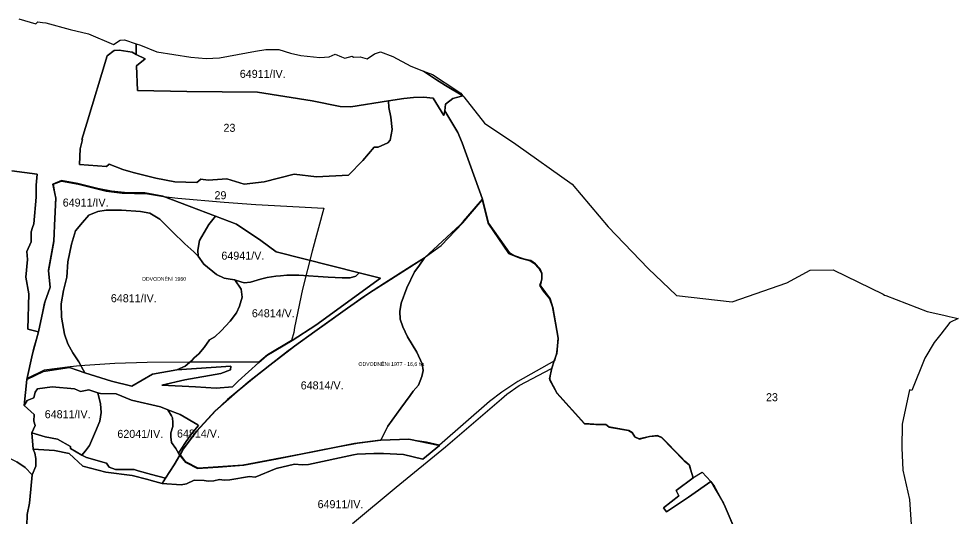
# Model space of a CAD drawing. Extents: x -521621 to -516761, y -1190184 to -1184927.
# Drawn here: x -518679 to -516919, y -1186003 to -1185071 of the extents above; entities that cross this region are included whole.
import ezdxf

# ---------------------------------------------------------------- set-up
doc = ezdxf.new("R2010")
doc.units = 0
doc.layers.add('BPEJ_s', color=7, linetype='Continuous')
doc.layers.add('odvodneni_s', color=7, linetype='Continuous')

msp = doc.modelspace()

# ---------------------------------------------------------------- linework, layer by layer
at = {"layer": 'BPEJ_s'}
for points in [[(-518679, -1185071.3), (-518647.2, -1185080.5), (-518643.2, -1185077.1), (-518634.5, -1185078.2), (-518628.2, -1185079.1), (-518582.7, -1185091.5), (-518548.4, -1185099.6), (-518501.4, -1185119.5), (-518489.2, -1185111.4), (-518480.6, -1185110.5), (-518459.1, -1185118.3), (-518459, -1185138.2), (-518466.2, -1185134), (-518491.1, -1185130.2), (-518500.3, -1185130.4), (-518513.4, -1185140.4), (-518551.6, -1185266.9), (-518560.8, -1185297), (-518559.4, -1185297.5), (-518563.8, -1185315), (-518565.4, -1185344.1), (-518514.8, -1185348.1), (-518509.7, -1185343.3), (-518484.1, -1185353.2), (-518464.8, -1185359.2), (-518421.9, -1185369.5), (-518386.4, -1185376.4), (-518345.6, -1185377.5), (-518337.7, -1185371.7), (-518324.2, -1185373.5), (-518289, -1185370.8), (-518256.6, -1185380.8), (-518219.2, -1185376.4), (-518163.2, -1185362.1), (-518121.4, -1185367.5), (-518060.9, -1185364), (-518034.2, -1185336.9), (-518013.4, -1185311.7), (-518005.8, -1185311.4), (-517987.2, -1185303.4), (-517983.2, -1185298.5), (-517979.6, -1185278.5), (-517981.6, -1185255.6), (-517985.7, -1185237.6), (-517986.1, -1185224.9), (-517957.4, -1185220.3), (-517939.5, -1185218.8), (-517920.8, -1185218.3), (-517902.4, -1185219.9), (-517882.7, -1185252.1), (-517880.7, -1185243.4), (-517856.1, -1185284), (-517848.3, -1185303.8), (-517810.2, -1185409.1), (-517845.7, -1185450.4), (-517851.9, -1185457.2), (-517918.9, -1185518.6), (-517943.6, -1185534.2), (-517993.6, -1185566.2), (-518025.5, -1185586.9), (-518063, -1185613), (-518124.5, -1185656.9), (-518162.4, -1185684.1), (-518208.8, -1185720), (-518241.2, -1185745.3), (-518288, -1185784.3), (-518310, -1185804.6), (-518346.2, -1185844), (-518370.7, -1185877), (-518377.1, -1185888.1), (-518379.6, -1185884.4), (-518373.5, -1185875.2), (-518366.3, -1185864.4), (-518355.6, -1185848.3), (-518342.1, -1185833.1), (-518343.5, -1185831.8), (-518376.8, -1185812.3), (-518399.9, -1185803.2), (-518413.6, -1185797.7), (-518468, -1185785.2), (-518496.6, -1185773.6), (-518525.7, -1185773), (-518530.9, -1185771.4), (-518547.9, -1185766.2), (-518563.4, -1185769), (-518574.7, -1185764.4), (-518616.5, -1185760.2), (-518643.8, -1185764.2), (-518648.3, -1185770.1), (-518650.8, -1185781.2), (-518663.1, -1185786), (-518669.1, -1185795.6), (-518664, -1185746.6), (-518632.5, -1185731.4), (-518583.8, -1185724.2), (-518555, -1185734.5), (-518505.4, -1185750.1), (-518467, -1185759), (-518428.2, -1185736.5), (-518382.8, -1185728.3), (-518281.6, -1185722), (-518282, -1185728.7), (-518300.5, -1185735.5), (-518368, -1185747.2), (-518410.8, -1185757.1), (-518347.6, -1185760.4), (-518309.2, -1185762.6), (-518278.6, -1185760.3), (-518267.9, -1185749.8), (-518229.3, -1185714.9), (-518213.9, -1185701.5), (-518166.7, -1185673.6), (-518122.2, -1185644.8), (-518001.2, -1185557), (-518041, -1185547), (-518196.6, -1185507.8), (-518225.5, -1185486.3), (-518270.8, -1185456.1), (-518310.3, -1185441), (-518409, -1185403.2), (-518442.6, -1185396.9), (-518480.8, -1185396.3), (-518505.2, -1185394.3), (-518530.8, -1185388.8), (-518568.4, -1185379.5), (-518598.8, -1185374.3), (-518615.3, -1185381.1), (-518609.5, -1185407.2), (-518612, -1185458.3), (-518613.3, -1185488.4), (-518623.3, -1185543.2), (-518620.4, -1185573.5), (-518629.8, -1185602.1), (-518641.9, -1185657.5), (-518662, -1185652.7), (-518660.1, -1185586.3), (-518665.4, -1185554.9), (-518662.7, -1185522.1), (-518664, -1185506.8), (-518655.9, -1185488.8), (-518655.7, -1185469.9), (-518653.2, -1185462.2), (-518650.9, -1185455.3), (-518646.4, -1185405.3), (-518646.1, -1185382.5), (-518644.7, -1185362.2), (-518692, -1185355.7)], [(-517323.2, -1186060.8), (-517357.4, -1185980.5), (-517373.4, -1185950.9), (-517375.6, -1185947.1), (-517382.3, -1185937.7), (-517424.2, -1185967), (-517465.3, -1185994.3), (-517471, -1185987), (-517442.6, -1185964.7), (-517447.2, -1185954.4), (-517415.7, -1185930.7), (-517422.7, -1185906.3), (-517430.9, -1185899.6), (-517437.9, -1185891.9), (-517474.4, -1185855.1), (-517482.6, -1185851.8), (-517497.5, -1185853.7), (-517516.5, -1185857.8), (-517525, -1185854.2), (-517529.9, -1185846), (-517536.1, -1185842.3), (-517573.7, -1185835.2), (-517579, -1185830.9), (-517592.9, -1185831.1), (-517619, -1185829.2), (-517670.8, -1185771.5), (-517684.5, -1185745.7), (-517680, -1185725.3), (-517675.6, -1185711.7), (-517671.2, -1185697.7), (-517668.6, -1185669), (-517678.5, -1185611.7), (-517683.6, -1185595.4), (-517700.8, -1185571.8), (-517701.8, -1185569.7), (-517698.7, -1185557.9), (-517698.7, -1185547.3), (-517702.7, -1185538.6), (-517710.9, -1185529.8), (-517719.3, -1185524), (-517731.6, -1185521.1), (-517751.5, -1185514.3), (-517759.6, -1185509.5), (-517799.1, -1185453.7), (-517810.2, -1185409.1), (-517848.3, -1185303.8), (-517856.1, -1185284), (-517880.7, -1185243.4), (-517879.4, -1185231.3), (-517865.9, -1185220.3), (-517846.8, -1185215.4), (-517845.4, -1185217.3), (-517806.7, -1185267), (-517747.8, -1185305.8), (-517642.2, -1185380.8), (-517574.8, -1185460.6), (-517499.9, -1185539), (-517446.5, -1185589.5), (-517342.5, -1185601.1), (-517240, -1185565.8), (-517196.5, -1185541.9), (-517153.2, -1185541.5), (-517059.7, -1185587.2), (-517057.2, -1185588.5), (-517054.6, -1185589.7), (-517016, -1185604.6), (-516977.3, -1185619.4), (-516946, -1185626.5), (-516936, -1185628.7), (-516918.9, -1185632.5), (-516934.4, -1185639.9), (-516951.6, -1185661.5), (-516964.2, -1185677.4), (-516981.2, -1185707), (-517005.8, -1185767.5), (-517010.3, -1185766.1), (-517023.9, -1185830.2), (-517024.8, -1185874.8), (-517022.7, -1185916.5), (-517010.1, -1185971.5), (-517003.7, -1186064.1)], [(-518692, -1185355.7), (-518644.7, -1185362.2), (-518646.1, -1185382.5), (-518646.4, -1185405.3), (-518650.9, -1185455.3), (-518653.2, -1185462.2), (-518655.7, -1185469.9), (-518655.9, -1185488.8), (-518664, -1185506.8), (-518662.7, -1185522.1), (-518665.4, -1185554.9), (-518660.1, -1185586.3), (-518662, -1185652.7), (-518641.9, -1185657.5), (-518653.2, -1185698.9), (-518664, -1185746.6), (-518669.1, -1185795.6), (-518650.1, -1185812.4), (-518650.6, -1185824.9), (-518648.2, -1185832.5), (-518654.3, -1185846.7), (-518651.9, -1185877), (-518648.8, -1185884.7), (-518647.2, -1185894.9), (-518646.8, -1185908.9), (-518653.6, -1185925.2), (-518666.9, -1185911.6), (-518682.3, -1185900.6)], [(-518663.9, -1186020.8), (-518663.3, -1185999.2), (-518658.6, -1185978.5), (-518656.2, -1185952.1), (-518653.6, -1185925.2), (-518646.8, -1185908.9), (-518647.2, -1185894.9), (-518648.8, -1185884.7), (-518651.9, -1185877), (-518611.8, -1185879.4), (-518584.7, -1185885.5), (-518558.6, -1185909.1), (-518516.1, -1185919.9), (-518466.5, -1185926.5), (-518437.2, -1185934.1), (-518431.1, -1185935.5), (-518410.3, -1185941.2), (-518374.6, -1185943.8), (-518364.4, -1185941.9), (-518350.4, -1185935.4), (-518331.8, -1185935.8), (-518323.9, -1185937), (-518313.7, -1185936.5), (-518303.1, -1185933.8), (-518294, -1185935.1), (-518283.4, -1185934.7), (-518246.4, -1185928.1), (-518236.3, -1185929.6), (-518196.9, -1185913.2), (-518162.3, -1185905.3), (-518147.9, -1185906.4), (-518135.9, -1185905.7), (-518052.1, -1185887.8), (-518044.7, -1185886.5), (-518013.7, -1185885.3), (-517995.8, -1185885.5), (-517958.2, -1185887.3), (-517921.7, -1185896.1), (-517891, -1185870), (-517948.4, -1185858.7), (-518000.9, -1185860.3), (-517987.2, -1185834), (-517963.3, -1185800.4), (-517945.9, -1185776.5), (-517940.1, -1185768.3), (-517930.3, -1185757.1), (-517923.9, -1185740.9), (-517921, -1185729.6), (-517922.9, -1185717.3), (-517933.2, -1185695.2), (-517950.9, -1185666.7), (-517959.2, -1185648.1), (-517964.6, -1185633.4), (-517965.1, -1185619.6), (-517962.7, -1185603.9), (-517951.9, -1185575), (-517937.8, -1185544.9), (-517929.2, -1185534.7), (-517918.9, -1185518.6), (-517851.9, -1185457.2), (-517845.7, -1185450.4), (-517810.2, -1185409.1), (-517799.1, -1185453.7), (-517759.6, -1185509.5), (-517751.5, -1185514.3), (-517731.6, -1185521.1), (-517719.3, -1185524), (-517710.9, -1185529.8), (-517702.7, -1185538.6), (-517698.7, -1185547.3), (-517698.7, -1185557.9), (-517701.8, -1185569.7), (-517700.8, -1185571.8), (-517683.6, -1185595.4), (-517678.5, -1185611.7), (-517668.6, -1185669), (-517671.2, -1185697.7), (-517675.6, -1185711.7), (-517680, -1185725.3), (-517684.5, -1185745.7), (-517670.8, -1185771.5), (-517619, -1185829.2), (-517592.9, -1185831.1), (-517579, -1185830.9), (-517573.7, -1185835.2), (-517536.1, -1185842.3), (-517529.9, -1185846), (-517525, -1185854.2), (-517516.5, -1185857.8), (-517497.5, -1185853.7), (-517482.6, -1185851.8), (-517474.4, -1185855.1), (-517437.9, -1185891.9), (-517430.9, -1185899.6), (-517422.7, -1185906.3), (-517415.7, -1185930.7), (-517447.2, -1185954.4), (-517442.6, -1185964.7), (-517471, -1185987), (-517465.3, -1185994.3), (-517424.2, -1185967), (-517382.3, -1185937.7), (-517375.6, -1185947.1), (-517373.4, -1185950.9), (-517357.4, -1185980.5), (-517323.2, -1186060.8)], [(-518758, -1186004.2), (-518755.3, -1185978.2), (-518749.1, -1185953.6), (-518738.2, -1185920.1), (-518722.8, -1185904.4), (-518704.5, -1185895), (-518694.1, -1185895.3), (-518682.3, -1185900.6), (-518666.9, -1185911.6), (-518653.6, -1185925.2), (-518656.2, -1185952.1), (-518658.6, -1185978.5), (-518663.3, -1185999.2), (-518663.9, -1186020.8)]]:
    msp.add_lwpolyline(points, dxfattribs=at)
for points in [[(-518459, -1185138.2), (-518442.2, -1185146.2), (-518458.1, -1185159.6), (-518456.5, -1185205.7), (-518364.3, -1185207.5), (-518231.7, -1185208.5), (-518129, -1185224.7), (-518076.5, -1185235.8), (-518057, -1185236.3), (-517986.1, -1185224.9), (-517985.7, -1185237.6), (-517981.6, -1185255.6), (-517979.6, -1185278.5), (-517983.2, -1185298.5), (-517987.2, -1185303.4), (-518005.8, -1185311.4), (-518013.4, -1185311.7), (-518034.2, -1185336.9), (-518060.9, -1185364), (-518121.4, -1185367.5), (-518163.2, -1185362.1), (-518219.2, -1185376.4), (-518256.6, -1185380.8), (-518289, -1185370.8), (-518324.2, -1185373.5), (-518337.7, -1185371.7), (-518345.6, -1185377.5), (-518386.4, -1185376.4), (-518421.9, -1185369.5), (-518464.8, -1185359.2), (-518484.1, -1185353.2), (-518509.7, -1185343.3), (-518514.8, -1185348.1), (-518565.4, -1185344.1), (-518563.8, -1185315), (-518559.4, -1185297.5), (-518560.8, -1185297), (-518551.6, -1185266.9), (-518513.4, -1185140.4), (-518500.3, -1185130.4), (-518491.1, -1185130.2), (-518466.2, -1185134)], [(-518459.1, -1185118.3), (-518450.7, -1185120.4), (-518420.2, -1185133.3), (-518356.7, -1185143.4), (-518327.9, -1185145.4), (-518302.8, -1185144.3), (-518235.6, -1185132.2), (-518216, -1185129), (-518191.5, -1185128.7), (-518169.8, -1185135.4), (-518150.8, -1185140.3), (-518114.6, -1185143.9), (-518097.6, -1185142.5), (-518086.4, -1185137.6), (-518074.5, -1185142.8), (-518068.2, -1185145.1), (-518054.6, -1185141.3), (-518051.7, -1185143.4), (-518039.3, -1185142.2), (-518026.3, -1185146.5), (-518012.5, -1185136.7), (-518001.2, -1185133), (-517978.2, -1185142.1), (-517944.2, -1185159.8), (-517936.5, -1185162.9), (-517928.9, -1185166.1), (-517920.5, -1185169.2), (-517898, -1185184.3), (-517879.4, -1185196.2), (-517846.8, -1185215.4), (-517865.9, -1185220.3), (-517879.4, -1185231.3), (-517880.7, -1185243.4), (-517882.7, -1185252.1), (-517902.4, -1185219.9), (-517920.8, -1185218.3), (-517939.5, -1185218.8), (-517957.4, -1185220.3), (-517986.1, -1185224.9), (-518057, -1185236.3), (-518076.5, -1185235.8), (-518129, -1185224.7), (-518231.7, -1185208.5), (-518364.3, -1185207.5), (-518456.5, -1185205.7), (-518458.1, -1185159.6), (-518442.2, -1185146.2), (-518459, -1185138.2)], [(-517920.5, -1185169.2), (-517903.8, -1185175.3), (-517858.2, -1185205.3), (-517850.7, -1185210.3), (-517846.8, -1185215.4), (-517879.4, -1185196.2), (-517898, -1185184.3)], [(-518664, -1185746.6), (-518653.2, -1185698.9), (-518641.9, -1185657.5), (-518629.8, -1185602.1), (-518620.4, -1185573.5), (-518623.3, -1185543.2), (-518613.3, -1185488.4), (-518612, -1185458.3), (-518609.5, -1185407.2), (-518615.3, -1185381.1), (-518598.8, -1185374.3), (-518568.4, -1185379.5), (-518530.8, -1185388.8), (-518505.2, -1185394.3), (-518480.8, -1185396.3), (-518442.6, -1185396.9), (-518409, -1185403.2), (-518310.3, -1185441), (-518322.7, -1185456.6), (-518340.4, -1185486.3), (-518343.2, -1185504.6), (-518342.6, -1185515.8), (-518351, -1185507.9), (-518368.1, -1185492.8), (-518391.1, -1185470.1), (-518414.6, -1185446.5), (-518433.6, -1185435.1), (-518451, -1185432.2), (-518486.6, -1185429.4), (-518515.1, -1185429.4), (-518530.5, -1185432.2), (-518547.9, -1185439), (-518559.6, -1185452.4), (-518572.5, -1185468.4), (-518580.4, -1185493.3), (-518587.2, -1185526.1), (-518589, -1185555), (-518594.9, -1185580), (-518599.7, -1185605.1), (-518598.7, -1185630.1), (-518593.4, -1185661.8), (-518587.2, -1185680.1), (-518577.5, -1185697), (-518566.3, -1185713.6), (-518561.6, -1185723.2), (-518555, -1185734.5), (-518583.8, -1185724.2), (-518632.5, -1185731.4)], [(-518555, -1185734.5), (-518561.6, -1185723.2), (-518566.3, -1185713.6), (-518577.5, -1185697), (-518587.2, -1185680.1), (-518593.4, -1185661.8), (-518598.7, -1185630.1), (-518599.7, -1185605.1), (-518594.9, -1185580), (-518589, -1185555), (-518587.2, -1185526.1), (-518580.4, -1185493.3), (-518572.5, -1185468.4), (-518559.6, -1185452.4), (-518547.9, -1185439), (-518530.5, -1185432.2), (-518515.1, -1185429.4), (-518486.6, -1185429.4), (-518451, -1185432.2), (-518433.6, -1185435.1), (-518414.6, -1185446.5), (-518391.1, -1185470.1), (-518368.1, -1185492.8), (-518351, -1185507.9), (-518342.6, -1185515.8), (-518332.5, -1185530.6), (-518308.2, -1185550.2), (-518294.4, -1185556.9), (-518282.9, -1185558.5), (-518274.1, -1185560.1), (-518262.4, -1185577.4), (-518260.5, -1185592.4), (-518265.3, -1185609.4), (-518270.9, -1185621.8), (-518282.6, -1185637.4), (-518299.6, -1185655.4), (-518311.6, -1185666.5), (-518321.4, -1185672.3), (-518331.5, -1185686.7), (-518341.3, -1185698.7), (-518350.3, -1185706.3), (-518354.6, -1185711.4), (-518367, -1185722), (-518382.8, -1185728.3), (-518428.2, -1185736.5), (-518467, -1185759), (-518505.4, -1185750.1)], [(-518342.6, -1185515.8), (-518343.2, -1185504.6), (-518340.4, -1185486.3), (-518322.7, -1185456.6), (-518310.3, -1185441), (-518270.8, -1185456.1), (-518225.5, -1185486.3), (-518196.6, -1185507.8), (-518041, -1185547), (-518047.4, -1185553), (-518058.2, -1185556.2), (-518073.2, -1185556.5), (-518099.4, -1185554.8), (-518117.9, -1185554.1), (-518154.2, -1185551.3), (-518176.5, -1185551.6), (-518188.7, -1185552.3), (-518197.2, -1185553), (-518213.8, -1185555.6), (-518226.2, -1185558.8), (-518245.1, -1185564.7), (-518256.9, -1185565.7), (-518271.2, -1185561.1), (-518274.1, -1185560.1), (-518282.9, -1185558.5), (-518294.4, -1185556.9), (-518308.2, -1185550.2), (-518332.5, -1185530.6)], [(-518377.1, -1185888.1), (-518370.7, -1185877), (-518346.2, -1185844), (-518310, -1185804.6), (-518288, -1185784.3), (-518241.2, -1185745.3), (-518208.8, -1185720), (-518162.4, -1185684.1), (-518124.5, -1185656.9), (-518063, -1185613), (-518025.5, -1185586.9), (-517993.6, -1185566.2), (-517943.6, -1185534.2), (-517918.9, -1185518.6), (-517929.2, -1185534.7), (-517937.8, -1185544.9), (-517951.9, -1185575), (-517962.7, -1185603.9), (-517965.1, -1185619.6), (-517964.6, -1185633.4), (-517959.2, -1185648.1), (-517950.9, -1185666.7), (-517933.2, -1185695.2), (-517922.9, -1185717.3), (-517921, -1185729.6), (-517923.9, -1185740.9), (-517930.3, -1185757.1), (-517940.1, -1185768.3), (-517945.9, -1185776.5), (-517963.3, -1185800.4), (-517987.2, -1185834), (-518000.9, -1185860.3), (-518044.4, -1185865.8), (-518081.4, -1185872.7), (-518194.5, -1185895.1), (-518257.2, -1185907.1), (-518305.1, -1185910.7), (-518344.2, -1185913.2), (-518366.2, -1185902.4)], [(-518382.8, -1185728.3), (-518367, -1185722), (-518354.6, -1185711.4), (-518350.3, -1185706.3), (-518341.3, -1185698.7), (-518331.5, -1185686.7), (-518321.4, -1185672.3), (-518311.6, -1185666.5), (-518299.6, -1185655.4), (-518282.6, -1185637.4), (-518270.9, -1185621.8), (-518265.3, -1185609.4), (-518260.5, -1185592.4), (-518262.4, -1185577.4), (-518274.1, -1185560.1), (-518271.2, -1185561.1), (-518256.9, -1185565.7), (-518245.1, -1185564.7), (-518226.2, -1185558.8), (-518213.8, -1185555.6), (-518197.2, -1185553), (-518188.7, -1185552.3), (-518176.5, -1185551.6), (-518154.2, -1185551.3), (-518117.9, -1185554.1), (-518099.4, -1185554.8), (-518073.2, -1185556.5), (-518058.2, -1185556.2), (-518047.4, -1185553), (-518041, -1185547), (-518001.2, -1185557), (-518122.2, -1185644.8), (-518166.7, -1185673.6), (-518213.9, -1185701.5), (-518229.3, -1185714.9), (-518267.9, -1185749.8), (-518278.6, -1185760.3), (-518309.2, -1185762.6), (-518347.6, -1185760.4), (-518410.8, -1185757.1), (-518368, -1185747.2), (-518300.5, -1185735.5), (-518282, -1185728.7), (-518281.6, -1185722)], [(-518669.1, -1185795.6), (-518663.1, -1185786), (-518650.8, -1185781.2), (-518648.3, -1185770.1), (-518643.8, -1185764.2), (-518616.5, -1185760.2), (-518574.7, -1185764.4), (-518563.4, -1185769), (-518547.9, -1185766.2), (-518530.9, -1185771.4), (-518525.7, -1185792.4), (-518524.6, -1185808.4), (-518527.3, -1185825), (-518535, -1185844.3), (-518546.2, -1185870.1), (-518553.9, -1185880.1), (-518560.5, -1185888.1), (-518582.2, -1185875.8), (-518582, -1185872), (-518606.4, -1185858.4), (-518629.6, -1185854.3), (-518654.3, -1185846.7), (-518648.2, -1185832.5), (-518650.6, -1185824.9), (-518650.1, -1185812.4)], [(-518560.5, -1185888.1), (-518553.9, -1185880.1), (-518546.2, -1185870.1), (-518535, -1185844.3), (-518527.3, -1185825), (-518524.6, -1185808.4), (-518525.7, -1185792.4), (-518530.9, -1185771.4), (-518525.7, -1185773), (-518496.6, -1185773.6), (-518468, -1185785.2), (-518413.6, -1185797.7), (-518399.9, -1185803.2), (-518393, -1185814.4), (-518391.1, -1185818.6), (-518390.3, -1185826.9), (-518390.3, -1185834.8), (-518393.8, -1185846.3), (-518394.1, -1185854), (-518392.8, -1185864.9), (-518384.7, -1185875.6), (-518379.6, -1185884.4), (-518377.1, -1185888.1), (-518387.9, -1185906.2), (-518403.9, -1185931.7), (-518430.1, -1185924.7), (-518455.2, -1185917.4), (-518462.8, -1185915.2), (-518467.9, -1185915.1), (-518497.9, -1185915.3), (-518509.8, -1185910.8), (-518514.7, -1185903.4), (-518552.2, -1185892.7)], [(-518399.9, -1185803.2), (-518376.8, -1185812.3), (-518343.5, -1185831.8), (-518342.1, -1185833.1), (-518355.6, -1185848.3), (-518366.3, -1185864.4), (-518373.5, -1185875.2), (-518379.6, -1185884.4), (-518384.7, -1185875.6), (-518392.8, -1185864.9), (-518394.1, -1185854), (-518393.8, -1185846.3), (-518390.3, -1185834.8), (-518390.3, -1185826.9), (-518391.1, -1185818.6), (-518393, -1185814.4)], [(-518654.3, -1185846.7), (-518629.6, -1185854.3), (-518606.4, -1185858.4), (-518582, -1185872), (-518582.2, -1185875.8), (-518560.5, -1185888.1), (-518552.2, -1185892.7), (-518514.7, -1185903.4), (-518509.8, -1185910.8), (-518497.9, -1185915.3), (-518467.9, -1185915.1), (-518462.8, -1185915.2), (-518455.2, -1185917.4), (-518430.1, -1185924.7), (-518403.9, -1185931.7), (-518410.3, -1185941.2), (-518431.1, -1185935.5), (-518437.2, -1185934.1), (-518466.5, -1185926.5), (-518516.1, -1185919.9), (-518558.6, -1185909.1), (-518584.7, -1185885.5), (-518611.8, -1185879.4), (-518651.9, -1185877)], [(-518410.3, -1185941.2), (-518403.9, -1185931.7), (-518387.9, -1185906.2), (-518377.1, -1185888.1), (-518366.2, -1185902.4), (-518344.2, -1185913.2), (-518305.1, -1185910.7), (-518257.2, -1185907.1), (-518194.5, -1185895.1), (-518081.4, -1185872.7), (-518044.4, -1185865.8), (-518000.9, -1185860.3), (-517948.4, -1185858.7), (-517891, -1185870), (-517921.7, -1185896.1), (-517958.2, -1185887.3), (-517995.8, -1185885.5), (-518013.7, -1185885.3), (-518044.7, -1185886.5), (-518052.1, -1185887.8), (-518135.9, -1185905.7), (-518147.9, -1185906.4), (-518162.3, -1185905.3), (-518196.9, -1185913.2), (-518236.3, -1185929.6), (-518246.4, -1185928.1), (-518283.4, -1185934.7), (-518294, -1185935.1), (-518303.1, -1185933.8), (-518313.7, -1185936.5), (-518323.9, -1185937), (-518331.8, -1185935.8), (-518350.4, -1185935.4), (-518364.4, -1185941.9), (-518374.6, -1185943.8)]]:
    msp.add_lwpolyline(points, close=True, dxfattribs=at)
at = {"layer": 'odvodneni_s'}
for points in [[(-518663.4, -1185744.9), (-518650.8, -1185688.3), (-518641.6, -1185656.3), (-518630.7, -1185603.7), (-518620.4, -1185573.6), (-518623.3, -1185541.7), (-518613.4, -1185486.8), (-518609.4, -1185406.2), (-518614, -1185380.8), (-518599, -1185375.6), (-518567.4, -1185380.9), (-518515, -1185393.9), (-518485, -1185397.8), (-518462.2, -1185398.4), (-518441.6, -1185398.3), (-518407.7, -1185404.2), (-518381.1, -1185406.9), (-518294.3, -1185414.5), (-518235.1, -1185419.3), (-518107.3, -1185426), (-518129.2, -1185506.1), (-518147.3, -1185577.7), (-518162.6, -1185649.2), (-518163.6, -1185658.8), (-518167.7, -1185673.9), (-518212.9, -1185700.8), (-518229.1, -1185714.4), (-518358.1, -1185714.4), (-518438.6, -1185714.9), (-518498.8, -1185716.7), (-518564.4, -1185720.9), (-518582.4, -1185723.2), (-518631.4, -1185729.3)], [(-518375.8, -1185887.9), (-518370.1, -1185877.1), (-518345.9, -1185843.6), (-518310.7, -1185805.2), (-518249.2, -1185750.8), (-518174.4, -1185692.5), (-518092, -1185633.6), (-518034.8, -1185592.7), (-517996.1, -1185568.4), (-517923.9, -1185522.2), (-517887.7, -1185495.7), (-517846.7, -1185453.4), (-517810.6, -1185410.6), (-517800.3, -1185453.9), (-517761.5, -1185510.5), (-517754, -1185514.1), (-517739.8, -1185519.5), (-517721, -1185524.5), (-517714.2, -1185528.8), (-517704.3, -1185538.8), (-517699.1, -1185548.7), (-517699.1, -1185558.5), (-517703.2, -1185570.5), (-517696.6, -1185581.1), (-517684.4, -1185595.8), (-517679.4, -1185610.3), (-517668.5, -1185671.7), (-517671.9, -1185700), (-517675.3, -1185711.7), (-517743.7, -1185750.2), (-517774.2, -1185770.4), (-517797.3, -1185788), (-517890.8, -1185869.4), (-517914.8, -1185864), (-517949.2, -1185859), (-518001.9, -1185860.1), (-518050.2, -1185866.5), (-518150.3, -1185886.3), (-518259.2, -1185907.1), (-518342.9, -1185912.8), (-518366.1, -1185901)]]:
    msp.add_lwpolyline(points, close=True, dxfattribs=at)
msp.add_lwpolyline([(-518053.6, -1186016), (-517971.7, -1185948.3), (-517879.6, -1185872.8), (-517774.6, -1185782.6), (-517764.7, -1185774.2), (-517741.5, -1185757.9), (-517680.7, -1185726.3), (-517684.8, -1185747.2), (-517671.2, -1185772.3), (-517619.3, -1185829.4), (-517598.1, -1185830.9), (-517579.1, -1185830.8), (-517573.5, -1185835.7), (-517536.9, -1185842.3), (-517530.1, -1185845.9), (-517525.6, -1185854.3), (-517516.2, -1185858.2), (-517497.3, -1185853.7), (-517482.5, -1185851.9), (-517474.7, -1185855.2), (-517432.1, -1185899), (-517422.5, -1185907.1), (-517416.2, -1185931.1), (-517398.9, -1185920), (-517382.6, -1185937.9), (-517382.6, -1185937.9), (-517376.7, -1185947.9), (-517374.3, -1185952), (-517358.7, -1185978.4), (-517323.9, -1186061.4)], dxfattribs=at)

# ---------------------------------------------------------------- texts
at = {"layer": 'BPEJ_s'}
for s, height, p in [('64911/IV.', 15, (-518264.8, -1185181.9)), ('23', 0.0647, (-517886.4, -1185188)), ('23', 15, (-518295.4, -1185282.9)), ('29', 15, (-518312.2, -1185409.1)), ('64911/IV.', 15, (-518596.6, -1185422.9)), ('64941/V.', 15, (-518299.3, -1185522.3)), ('64811/IV.', 15, (-518506.4, -1185602)), ('64814/V.', 15, (-518242.2, -1185630.1)), ('64814/V.', 15, (-518150.7, -1185765.2)), ('23', 15, (-517279, -1185787.3)), ('64811/IV.', 15, (-518630.3, -1185819.2)), ('62041/IV.', 15, (-518494.2, -1185856)), ('64814/V.', 15, (-518382.5, -1185855.4)), ('35', 0.0647, (-518551.9, -1185894.1)), ('29', 0.0647, (-518159.4, -1185899)), ('64911/IV.', 15, (-518119.1, -1185987.6))]:
    msp.add_text(s, height=height, dxfattribs=at).set_placement(p)
at = {"layer": 'odvodneni_s'}
for s, p in [('ODVODNĚNí 1960', (-518448.2, -1185561.9)), ('ODVODNĚNí 1977 - 16,6 ha', (-518042.6, -1185721.2))]:
    msp.add_text(s, height=7, dxfattribs=at).set_placement(p)

doc.saveas('drawing.dxf')
